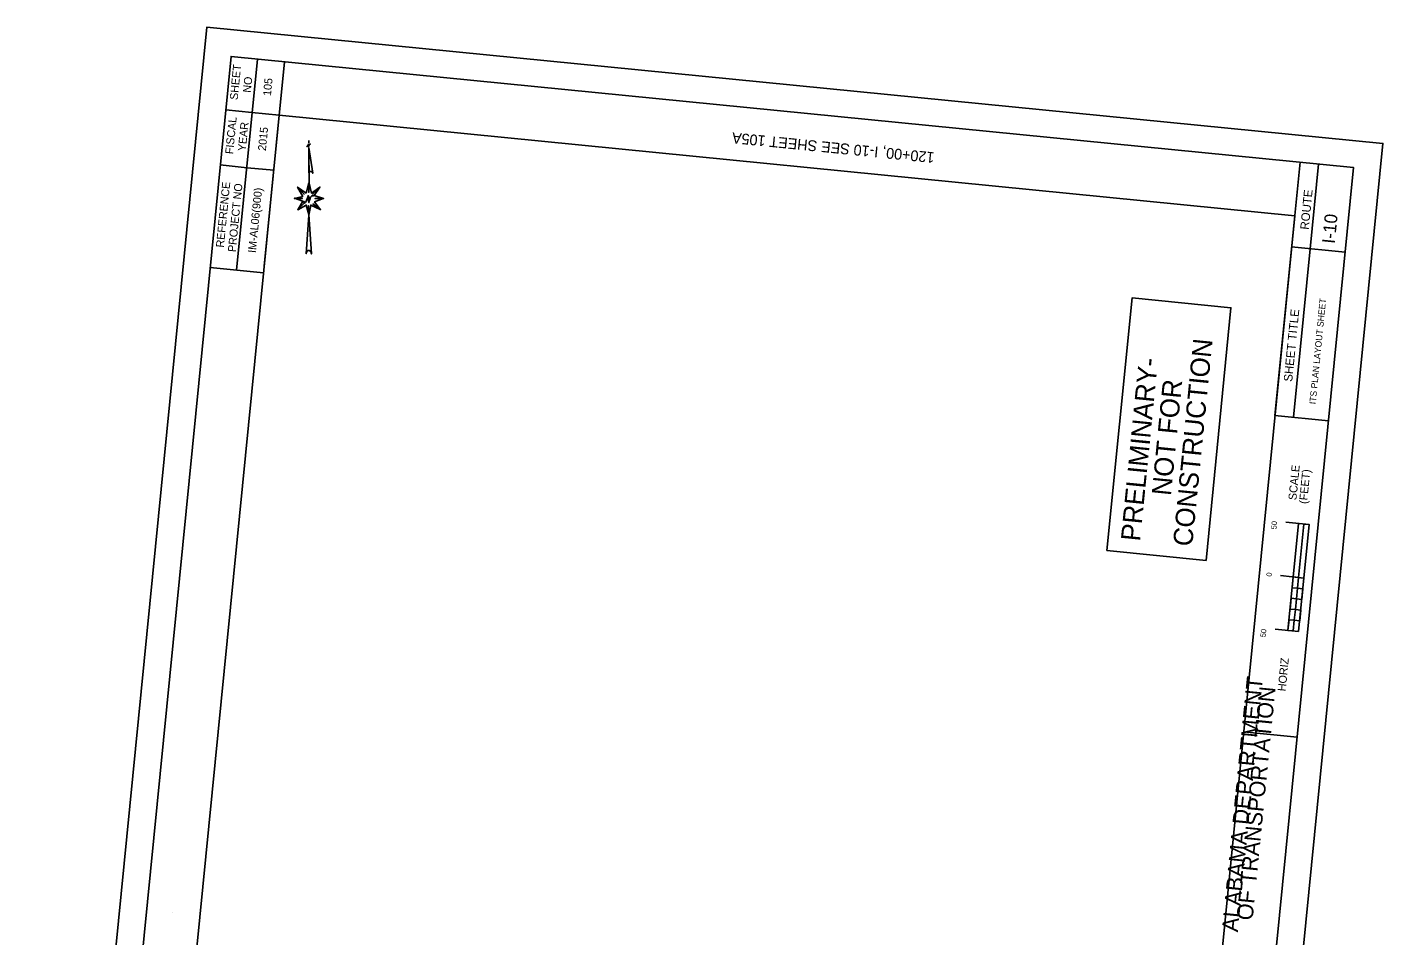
# Model space of a CAD drawing. Extents: x 1796928 to 1798191, y 245238 to 247038.
# Drawn here: x 1796928 to 1798191, y 246192 to 247038 of the extents above; entities that cross this region are included whole.
import ezdxf

# ---------------------------------------------------------------- set-up
doc = ezdxf.new("R2010")
doc.units = 0
for name, color, linetype in [('1', 7, 'Continuous'), ('ANNO-SHT', 7, 'Continuous'), ('ANNO-SYMB', 7, 'Continuous'), ('ANNO-TXT', 7, 'Continuous'), ('DRAINAGE', 7, 'Continuous'), ('Level 1', 7, 'Continuous'), ('Level 57', 7, 'Continuous'), ('Level 6', 7, 'Continuous'), ('Level 62', 7, 'Continuous'), ('SHT-BDR', 7, 'Continuous'), ('SHT-BNDRY', 7, 'Continuous')]:
    doc.layers.add(name, color=color, linetype=linetype)

# ---------------------------------------------------------------- blocks, each defined once
blk = doc.blocks.new('SC47208')
at = {"layer": 'Level 1'}
blk.add_line((0, 0), (0, 0), dxfattribs=at)

msp = doc.modelspace()

# ---------------------------------------------------------------- linework, layer by layer
at = {"layer": '1'}
msp.add_lwpolyline([(1797933.7, 246550.4), (1797957, 246785.6), (1798049.1, 246776.5), (1798025.9, 246541.3)], close=True, dxfattribs=at)
at = {"layer": 'ANNO-SYMB'}
for p, q in [((1798122, 246574.6), (1798100.1, 246576.8)), ((1798112, 246575.6), (1798102.2, 246476.1)), ((1798122, 246574.6), (1798112.1, 246475.1)), ((1798122, 246574.6), (1798117, 246575.1)), ((1798122, 246574.6), (1798117, 246575.1)), ((1798122, 246574.6), (1798117, 246575.1)), ((1798117, 246524.9), (1798095.2, 246527.1)), ((1798117, 246524.9), (1798095.2, 246527.1)), ((1798117, 246524.9), (1798095.2, 246527.1)), ((1798112.1, 246525.4), (1798107.1, 246525.9)), ((1798112.1, 246525.4), (1798107.1, 246525.9)), ((1798112.1, 246525.4), (1798107.1, 246525.9)), ((1798112.1, 246525.4), (1798110.1, 246505.5)), ((1798108.1, 246485.6), (1798103.2, 246486.1)), ((1798108.1, 246485.6), (1798103.2, 246486.1)), ((1798112.1, 246475.1), (1798090.2, 246477.3))]:
    msp.add_line(p, q, dxfattribs=at)
for points in [[(1798112.1, 246525.4), (1798117, 246575.1), (1798122, 246574.6), (1798117, 246524.9)], [(1798106.1, 246515.9), (1798107.1, 246525.9), (1798112.1, 246525.4), (1798111.1, 246515.4)], [(1798104.1, 246496), (1798105.1, 246506), (1798110.1, 246505.5), (1798109.1, 246495.5)], [(1798110.1, 246505.5), (1798111.1, 246515.4), (1798116.1, 246514.9), (1798115.1, 246505)], [(1798108.1, 246485.6), (1798109.1, 246495.5), (1798114.1, 246495), (1798113.1, 246485.1)], [(1798102.2, 246476.1), (1798103.2, 246486.1), (1798108.1, 246485.6), (1798107.1, 246475.6)]]:
    msp.add_lwpolyline(points, close=True, dxfattribs=at)
at = {"layer": 'ANNO-TXT'}
for p, q in [((1798122.9, 246831.4), (1798130.7, 246910.1)), ((1798107.4, 246674.5), (1798122.9, 246831.4))]:
    msp.add_line(p, q, dxfattribs=at)
at = {"layer": 'Level 57'}
msp.add_line((1797190.8, 246932.2), (1797190.7, 246929.8), dxfattribs=at)
for points in [[(1797191.9, 246928.7), (1797191.8, 246928.6), (1797191.9, 246928.5), (1797192, 246928.6), (1797192, 246928.8), (1797191.7, 246928.8), (1797191.5, 246928.7), (1797191.3, 246928.5), (1797191.1, 246928.2), (1797191, 246927.8), (1797190.8, 246927.2), (1797190.7, 246927), (1797190.6, 246926.6), (1797190.6, 246927.2), (1797190.6, 246928.2), (1797190.4, 246928.8), (1797190.4, 246928.2), (1797190.6, 246926.6), (1797190.6, 246928.2), (1797190.4, 246928.8), (1797190.2, 246928.2), (1797189.9, 246927.2), (1797189.6, 246926.6), (1797189.3, 246926.6), (1797189.1, 246926.6), (1797189, 246926.6), (1797189, 246926.8), (1797189.1, 246926.9), (1797189.2, 246926.9), (1797189.1, 246926.7)], [(1797190.7, 246925.7), (1797194.4, 246901.6), (1797194.2, 246902.3), (1797194, 246902.6), (1797193.6, 246903), (1797193.1, 246903.2), (1797192.8, 246903.3), (1797192.4, 246903.3), (1797192, 246903.3), (1797191.8, 246903.2), (1797191.4, 246903), (1797191.1, 246902.8), (1797190.9, 246902.5), (1797190.8, 246902.2), (1797190.7, 246902.1), (1797190.7, 246925.5), (1797190.9, 246892.6)], [(1797190.8, 246892.6), (1797190.6, 246883.7), (1797190.8, 246892.7), (1797188.1, 246883.1), (1797180.2, 246888.7), (1797186.3, 246882), (1797180.2, 246888.7), (1797185.1, 246880.1), (1797177.1, 246878.2), (1797184.8, 246878), (1797177.3, 246878.3), (1797185, 246875.5), (1797180.4, 246867.7), (1797186.2, 246873.4), (1797180.4, 246867.7), (1797188.3, 246872), (1797190.6, 246863.1), (1797190.5, 246871.5), (1797190.6, 246862.9), (1797192.6, 246871.9), (1797201.6, 246867.8), (1797192.5, 246871.9), (1797190.6, 246862.7), (1797188.3, 246826.7), (1797188.5, 246827.8), (1797188.8, 246828.6), (1797189.3, 246829.1), (1797189.9, 246829.6), (1797190.4, 246829.7), (1797191.1, 246829.7), (1797191.6, 246829.5), (1797192.1, 246829.2), (1797192.5, 246828.7), (1797192.9, 246828), (1797193, 246827.5), (1797193.2, 246826.6), (1797190.7, 246863.2), (1797192.5, 246872), (1797201.4, 246867.8), (1797194.6, 246873.1), (1797201.3, 246868), (1797196.1, 246875), (1797204.1, 246878.1), (1797196.5, 246878), (1797204.4, 246878.1), (1797195.6, 246880.8), (1797201.1, 246888.7), (1797194.6, 246882.3), (1797201.1, 246888.7), (1797193.1, 246883.1), (1797190.9, 246892.5)], [(1797194.6, 246880.6), (1797194.4, 246880.4), (1797194.7, 246880.2), (1797194.9, 246880.5), (1797194.8, 246880.9), (1797194.7, 246881), (1797194, 246880.9), (1797193.4, 246880.7), (1797192.4, 246879.4), (1797192.3, 246879), (1797191.9, 246877.8), (1797191.5, 246876.5), (1797191, 246875.7), (1797190.8, 246874.3), (1797190.8, 246876), (1797190.6, 246878.3), (1797190.5, 246879.5), (1797190, 246880.9), (1797190, 246879.2), (1797190.3, 246876.9), (1797190.5, 246875.5), (1797190.8, 246874.3), (1797190.8, 246876.4), (1797190.6, 246879.5), (1797190, 246880.9), (1797189.7, 246879.4), (1797189.1, 246877.8), (1797188.8, 246877.2), (1797188.5, 246876.3), (1797188.1, 246875.6), (1797187.8, 246875.1), (1797187.6, 246874.5), (1797186.8, 246874.1), (1797186.1, 246874.3), (1797185.9, 246874.5), (1797185.8, 246875.2), (1797186.2, 246875.5), (1797186.5, 246875.2), (1797186.3, 246874.9)]]:
    msp.add_lwpolyline(points, dxfattribs=at)
at = {"layer": 'Level 6'}
for p, q in [((1797142.9, 247007.8), (1797123.5, 246811.5)), ((1797168, 247005.4), (1797149.2, 246815)), ((1797137.6, 246958.1), (1797113.4, 246960.5)), ((1797137.6, 246958.1), (1797163.1, 246955.6)), ((1797133.2, 246906.8), (1797108.3, 246909.3)), ((1798113.4, 246911.8), (1798090.1, 246676.3)), ((1797133.2, 246906.8), (1797158, 246904.4)), ((1797098.9, 246813.9), (1797148.6, 246809))]:
    msp.add_line(p, q, dxfattribs=at)
at = {"layer": 'Level 62'}
msp.add_lwpolyline([(1798023.1, 245237.6), (1798190.5, 246929.3), (1797095.9, 247037.6), (1796928.5, 245345.9)], close=True, dxfattribs=at)
at = {"layer": 'SHT-BDR'}
msp.add_lwpolyline([(1797960.8, 245369.3), (1798108.5, 246862), (1797163.1, 246955.6), (1797015.4, 245462.9)], close=True, dxfattribs=at)
at = {"layer": 'SHT-BNDRY'}
for p, q in [((1798155.4, 246828.2), (1798105.6, 246833.1)), ((1798139.9, 246671.3), (1798090.1, 246676.3)), ((1798110.8, 246376.8), (1798060.9, 246381.7))]:
    msp.add_line(p, q, dxfattribs=at)
msp.add_lwpolyline([(1798004.4, 245302.2), (1798163.2, 246906.9), (1797118.3, 247010.3), (1796959.5, 245405.6)], close=True, dxfattribs=at)

# ---------------------------------------------------------------- block references
at = {"layer": 'DRAINAGE', "xscale": 1.0000020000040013, "yscale": 1.0000020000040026, "rotation": -32.06753455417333}
msp.add_blockref('SC47208', (1797063.6, 246213.4), dxfattribs=at)
msp.add_blockref('SC47208', (1797063.6, 246213.4), dxfattribs=at)

# ---------------------------------------------------------------- texts
at = {"layer": '1'}
for s, p in [('CONSTRUCTION', (1798013, 246553.8)), ('PRELIMINARY-', (1797964.5, 246558.6)), ('NOT FOR', (1797993.2, 246601))]:
    msp.add_text(s, height=18, rotation=84.3491, dxfattribs=at).set_placement(p)
at = {"layer": 'ANNO-SHT'}
for s, height, rotation, p in [('105', 7.45, 84.3491, (1797155.4, 246973.3)), ('2015', 7.45, 84.3491, (1797150.7, 246922.2)), ('120+00, I-10 SEE SHEET 105A', 10, 174.3491, (1797773.5, 246921)), ('IM-AL06(900)', 7.449, 84.3491, (1797141.4, 246827.2)), ('  I-10  ', 12, 84.3491, (1798144.9, 246826.8)), ('ITS PLAN LAYOUT SHEET', 6, 84.3491, (1798128, 246686.4))]:
    msp.add_text(s, height=height, rotation=rotation, dxfattribs=at).set_placement(p)
at = {"layer": 'ANNO-SYMB'}
for s, height, p in [('SCALE', 7.5, (1798110, 246597.1)), ('(FEET)', 7.5, (1798119.9, 246593.6)), (' 50', 5, (1798091.2, 246568.1)), ('0', 5, (1798087, 246526)), ('0', 5, (1798087, 246526)), ('0', 5, (1798087, 246526)), (' 50', 5, (1798081.2, 246467.7)), ('HORIZ', 7.5, (1798100, 246419.2))]:
    msp.add_text(s, height=height, rotation=84.4063, dxfattribs=at).set_placement(p)
at = {"layer": 'ANNO-TXT'}
for s, height, p in [('ROUTE', 8, (1798121.5, 246848.8)), ('SHEET TITLE', 8, (1798106.1, 246707.3)), ('ALABAMA DEPARTMENT', 15, (1798055.5, 246195)), ('OF TRANSPORTATION', 15, (1798069.2, 246205.8))]:
    msp.add_text(s, height=height, rotation=84.3491, dxfattribs=at).set_placement(p)
at = {"layer": 'Level 6'}
for s, p in [('SHEET', (1797124.5, 246969.6)), ('NO', (1797136.7, 246976.3)), ('FISCAL', (1797120.2, 246919.1)), ('YEAR', (1797132, 246921.9)), ('REFERENCE', (1797111.6, 246832.2)), ('PROJECT NO', (1797122.7, 246828))]:
    msp.add_text(s, height=7.44, rotation=84.3491, dxfattribs=at).set_placement(p)

doc.saveas('drawing.dxf')
